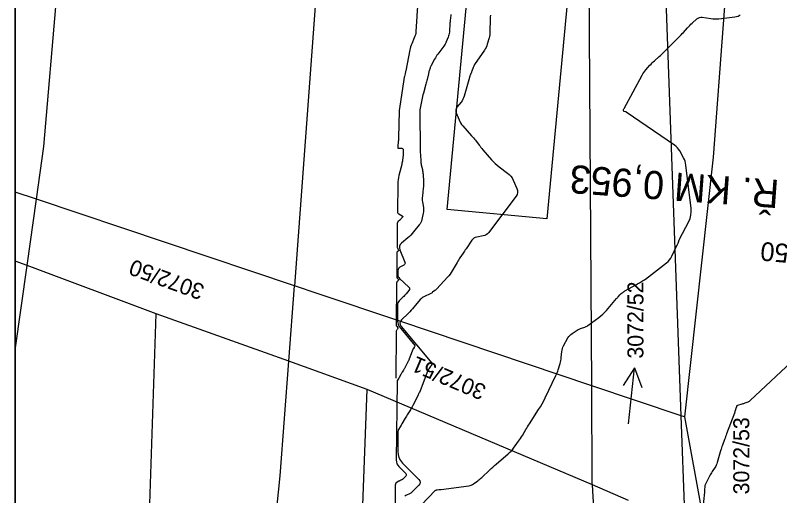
# Model space of a CAD drawing. Extents: x -534410 to -534262, y -1190162 to -1189584.
# Drawn here: x -534410.13 to -534369.46, y -1189643.39 to -1189617.8 of the extents above; entities that cross this region are included whole.
import ezdxf

# ---------------------------------------------------------------- set-up
doc = ezdxf.new("R2010")
doc.units = 0
for name, color, linetype in [('30', 7, 'Continuous'), ('31', 7, 'Continuous'), ('_N_text', 7, 'Continuous'), ('_přístup', 7, 'Continuous'), ('_rámeček', 7, 'Continuous'), ('_rámeček_mřížka', 7, 'Continuous'), ('Hranice parcel', 7, 'Continuous'), ('Parcelní čísla', 7, 'Continuous'), ('Pop  PČ popisy', 7, 'Continuous')]:
    doc.layers.add(name, color=color, linetype=linetype)

msp = doc.modelspace()

# ---------------------------------------------------------------- linework, layer by layer
at = {"layer": '30'}
for points in [[(-534386.954, -1189617.758), (-534386.98, -1189617.983), (-534386.986, -1189618.039), (-534386.992, -1189618.095), (-534386.997, -1189618.151), (-534387.001, -1189618.207), (-534387.035, -1189618.711), (-534387.043, -1189618.777), (-534387.055, -1189618.842), (-534387.072, -1189618.906), (-534387.095, -1189618.968), (-534387.197, -1189619.216), (-534387.224, -1189619.277), (-534387.255, -1189619.336), (-534387.289, -1189619.393), (-534387.328, -1189619.447), (-534387.649, -1189619.875), (-534387.695, -1189619.938), (-534387.738, -1189620.002), (-534387.779, -1189620.068), (-534387.818, -1189620.136), (-534388.005, -1189620.477), (-534388.022, -1189620.512), (-534388.038, -1189620.547), (-534388.052, -1189620.583), (-534388.063, -1189620.62), (-534388.106, -1189620.77), (-534388.117, -1189620.807), (-534388.127, -1189620.845), (-534388.136, -1189620.882), (-534388.145, -1189620.92), (-534388.214, -1189621.22), (-534388.229, -1189621.282), (-534388.245, -1189621.344), (-534388.261, -1189621.406), (-534388.278, -1189621.468), (-534388.414, -1189621.947), (-534388.438, -1189622.036), (-534388.46, -1189622.125), (-534388.481, -1189622.214), (-534388.5, -1189622.304), (-534388.573, -1189622.664), (-534388.589, -1189622.755), (-534388.6, -1189622.845), (-534388.607, -1189622.937), (-534388.609, -1189623.028), (-534388.606, -1189623.635), (-534388.605, -1189623.671), (-534388.605, -1189623.706), (-534388.604, -1189623.742), (-534388.602, -1189623.778), (-534388.597, -1189623.922), (-534388.595, -1189623.958), (-534388.595, -1189623.994), (-534388.594, -1189624.03), (-534388.594, -1189624.066), (-534388.59, -1189624.641), (-534388.589, -1189624.743), (-534388.588, -1189624.844), (-534388.585, -1189624.946), (-534388.581, -1189625.047), (-534388.56, -1189625.531), (-534388.556, -1189625.594), (-534388.549, -1189625.656), (-534388.539, -1189625.717), (-534388.527, -1189625.778), (-534388.471, -1189626.023), (-534388.458, -1189626.084), (-534388.448, -1189626.146), (-534388.44, -1189626.208), (-534388.435, -1189626.27), (-534388.411, -1189626.67), (-534388.407, -1189626.757), (-534388.408, -1189626.844), (-534388.412, -1189626.931), (-534388.42, -1189627.019), (-534388.469, -1189627.435), (-534388.475, -1189627.511), (-534388.476, -1189627.588), (-534388.472, -1189627.664), (-534388.462, -1189627.74), (-534388.415, -1189628.045), (-534388.406, -1189628.121), (-534388.405, -1189628.196), (-534388.411, -1189628.272), (-534388.424, -1189628.347), (-534388.498, -1189628.683), (-534388.52, -1189628.762), (-534388.551, -1189628.836), (-534388.59, -1189628.907), (-534388.638, -1189628.974), (-534388.938, -1189629.347), (-534389.007, -1189629.429), (-534389.08, -1189629.508), (-534389.156, -1189629.583), (-534389.236, -1189629.654), (-534389.576, -1189629.944), (-534389.644, -1189630.02), (-534389.681, -1189630.103), (-534389.687, -1189630.194), (-534389.663, -1189630.293), (-534389.404, -1189630.951), (-534389.392, -1189631.002), (-534389.398, -1189631.046), (-534389.421, -1189631.084), (-534389.463, -1189631.115), (-534389.668, -1189631.226), (-534389.712, -1189631.258), (-534389.744, -1189631.296), (-534389.763, -1189631.343), (-534389.77, -1189631.397), (-534389.772, -1189631.627), (-534389.768, -1189631.682), (-534389.752, -1189631.733), (-534389.726, -1189631.779), (-534389.689, -1189631.821), (-534389.193, -1189632.285), (-534389.159, -1189632.327), (-534389.146, -1189632.37), (-534389.154, -1189632.415), (-534389.183, -1189632.46), (-534389.34, -1189632.646), (-534389.38, -1189632.692), (-534389.421, -1189632.737), (-534389.463, -1189632.781), (-534389.506, -1189632.824), (-534389.697, -1189633.012), (-534389.738, -1189633.06), (-534389.767, -1189633.113), (-534389.785, -1189633.17), (-534389.791, -1189633.233), (-534389.798, -1189633.974), (-534389.788, -1189634.115), (-534389.754, -1189634.248), (-534389.697, -1189634.373), (-534389.616, -1189634.489), (-534388.866, -1189635.394), (-534388.861, -1189635.402), (-534388.859, -1189635.41), (-534388.86, -1189635.417), (-534388.865, -1189635.425), (-534388.888, -1189635.458), (-534388.899, -1189635.474), (-534388.91, -1189635.49), (-534388.948, -1189635.546), (-534388.955, -1189635.558), (-534388.962, -1189635.571), (-534388.968, -1189635.584), (-534388.974, -1189635.597), (-534389.136, -1189636.02), (-534389.145, -1189636.044), (-534389.155, -1189636.068), (-534389.165, -1189636.092), (-534389.175, -1189636.116), (-534389.215, -1189636.211), (-534389.226, -1189636.235), (-534389.236, -1189636.259), (-534389.248, -1189636.282), (-534389.259, -1189636.305), (-534389.401, -1189636.58), (-534389.416, -1189636.61), (-534389.433, -1189636.64), (-534389.45, -1189636.669), (-534389.468, -1189636.698), (-534389.54, -1189636.814), (-534389.558, -1189636.843), (-534389.575, -1189636.871), (-534389.593, -1189636.901), (-534389.61, -1189636.93), (-534389.708, -1189637.094), (-534389.726, -1189637.124), (-534389.762, -1189637.185), (-534389.798, -1189637.247), (-534389.805, -1189637.261), (-534389.81, -1189637.274), (-534389.813, -1189637.289), (-534389.814, -1189637.303), (-534389.856, -1189641.498), (-534389.848, -1189641.596), (-534389.822, -1189641.686), (-534389.778, -1189641.769), (-534389.716, -1189641.845), (-534389.355, -1189642.215), (-534389.331, -1189642.247), (-534389.323, -1189642.279), (-534389.331, -1189642.312), (-534389.355, -1189642.344), (-534389.516, -1189642.508), (-534389.531, -1189642.522), (-534389.546, -1189642.534), (-534389.562, -1189642.545), (-534389.579, -1189642.554), (-534389.651, -1189642.589), (-534389.668, -1189642.597), (-534389.686, -1189642.607), (-534389.703, -1189642.616), (-534389.72, -1189642.626), (-534389.857, -1189642.708), (-534389.863, -1189642.712), (-534389.868, -1189642.716), (-534389.872, -1189642.721), (-534389.875, -1189642.727), (-534389.894, -1189642.764), (-534389.903, -1189642.783), (-534389.906, -1189642.789), (-534389.908, -1189642.796), (-534389.916, -1189642.826), (-534389.917, -1189642.833), (-534389.918, -1189642.839), (-534389.919, -1189642.845), (-534389.919, -1189642.852), (-534389.936, -1189645.024)], [(-534388.521, -1189643.873), (-534387.781, -1189643.119), (-534387.761, -1189643.102), (-534387.739, -1189643.089), (-534387.715, -1189643.08), (-534387.689, -1189643.076), (-534387.579, -1189643.067), (-534387.552, -1189643.065), (-534387.525, -1189643.062), (-534387.498, -1189643.059), (-534387.471, -1189643.056), (-534385.999, -1189642.863), (-534385.931, -1189642.85), (-534385.867, -1189642.828), (-534385.805, -1189642.799), (-534385.748, -1189642.761), (-534385.522, -1189642.595), (-534385.467, -1189642.552), (-534385.413, -1189642.508), (-534385.36, -1189642.462), (-534385.308, -1189642.415), (-534384.897, -1189642.024), (-534384.81, -1189641.944), (-534384.723, -1189641.865), (-534384.635, -1189641.787), (-534384.546, -1189641.71), (-534383.905, -1189641.167), (-534383.826, -1189641.096), (-534383.752, -1189641.021), (-534383.683, -1189640.941), (-534383.618, -1189640.858), (-534383.349, -1189640.49), (-534383.297, -1189640.416), (-534383.246, -1189640.341), (-534383.197, -1189640.264), (-534383.149, -1189640.186), (-534382.964, -1189639.873), (-534382.918, -1189639.794), (-534382.87, -1189639.717), (-534382.822, -1189639.639), (-534382.773, -1189639.563), (-534382.283, -1189638.805), (-534382.187, -1189638.651), (-534382.097, -1189638.495), (-534382.011, -1189638.337), (-534381.93, -1189638.175), (-534381.361, -1189636.997), (-534381.326, -1189636.92), (-534381.294, -1189636.842), (-534381.265, -1189636.763), (-534381.239, -1189636.682), (-534381.14, -1189636.351), (-534381.119, -1189636.273), (-534381.102, -1189636.194), (-534381.089, -1189636.114), (-534381.08, -1189636.034), (-534381.052, -1189635.711), (-534381.041, -1189635.632), (-534381.022, -1189635.555), (-534380.994, -1189635.48), (-534380.959, -1189635.408), (-534380.725, -1189634.987), (-534380.682, -1189634.919), (-534380.631, -1189634.858), (-534380.574, -1189634.803), (-534380.509, -1189634.756), (-534380.176, -1189634.54), (-534380.136, -1189634.516), (-534380.095, -1189634.496), (-534380.053, -1189634.479), (-534380.009, -1189634.465), (-534379.832, -1189634.415), (-534379.788, -1189634.401), (-534379.747, -1189634.383), (-534379.707, -1189634.361), (-534379.669, -1189634.335), (-534379.079, -1189633.895), (-534378.971, -1189633.81), (-534378.867, -1189633.719), (-534378.77, -1189633.623), (-534378.677, -1189633.521), (-534378.134, -1189632.892), (-534378.114, -1189632.868), (-534378.094, -1189632.844), (-534378.074, -1189632.82), (-534378.054, -1189632.797), (-534377.973, -1189632.698), (-534377.953, -1189632.676), (-534377.932, -1189632.656), (-534377.91, -1189632.636), (-534377.887, -1189632.618), (-534377.791, -1189632.549), (-534377.767, -1189632.532), (-534377.742, -1189632.515), (-534377.717, -1189632.5), (-534377.691, -1189632.485), (-534377.07, -1189632.137), (-534377.031, -1189632.115), (-534376.992, -1189632.092), (-534376.952, -1189632.07), (-534376.913, -1189632.047), (-534376.756, -1189631.955), (-534376.718, -1189631.932), (-534376.68, -1189631.907), (-534376.643, -1189631.881), (-534376.606, -1189631.854), (-534375.485, -1189630.989), (-534375.396, -1189630.913), (-534375.318, -1189630.827), (-534375.251, -1189630.733), (-534375.195, -1189630.63), (-534374.911, -1189630.039), (-534374.899, -1189630.013), (-534374.888, -1189629.988), (-534374.878, -1189629.962), (-534374.868, -1189629.936), (-534374.83, -1189629.83), (-534374.82, -1189629.804), (-534374.809, -1189629.778), (-534374.797, -1189629.752), (-534374.785, -1189629.727), (-534374.3, -1189628.787), (-534374.229, -1189628.62), (-534374.184, -1189628.448), (-534374.166, -1189628.271), (-534374.174, -1189628.089), (-534374.45, -1189625.784), (-534374.467, -1189625.682), (-534374.494, -1189625.583), (-534374.531, -1189625.486), (-534374.577, -1189625.393), (-534374.781, -1189625.027), (-534374.836, -1189624.94), (-534374.9, -1189624.861), (-534374.973, -1189624.789), (-534375.055, -1189624.726), (-534377.622, -1189622.959), (-534377.633, -1189622.953), (-534377.644, -1189622.947), (-534377.656, -1189622.944), (-534377.668, -1189622.941), (-534377.728, -1189622.933), (-534377.735, -1189622.931), (-534377.741, -1189622.928), (-534377.747, -1189622.923), (-534377.752, -1189622.918), (-534377.773, -1189622.886), (-534377.775, -1189622.882), (-534377.776, -1189622.878), (-534377.777, -1189622.874), (-534377.778, -1189622.87), (-534377.778, -1189622.851), (-534377.778, -1189622.848), (-534377.777, -1189622.845), (-534377.776, -1189622.842), (-534377.775, -1189622.838), (-534377.769, -1189622.823), (-534377.766, -1189622.817), (-534377.764, -1189622.815), (-534377.746, -1189622.785), (-534377.74, -1189622.775), (-534377.738, -1189622.77), (-534376.78, -1189620.994), (-534376.738, -1189620.92), (-534376.691, -1189620.85), (-534376.641, -1189620.783), (-534376.586, -1189620.719), (-534376.36, -1189620.467), (-534376.302, -1189620.405), (-534376.243, -1189620.344), (-534376.183, -1189620.285), (-534376.121, -1189620.228), (-534375.869, -1189620.001), (-534375.806, -1189619.944), (-534375.745, -1189619.886), (-534375.684, -1189619.828), (-534375.623, -1189619.768), (-534374.819, -1189618.964), (-534374.76, -1189618.904), (-534374.701, -1189618.843), (-534374.643, -1189618.781), (-534374.586, -1189618.719), (-534374.36, -1189618.467), (-534374.302, -1189618.405), (-534374.243, -1189618.344), (-534374.183, -1189618.285), (-534374.121, -1189618.228), (-534373.869, -1189618.001), (-534373.803, -1189617.953), (-534373.733, -1189617.922), (-534373.657, -1189617.909), (-534373.576, -1189617.913), (-534373.119, -1189617.981), (-534373.015, -1189617.993), (-534372.911, -1189617.999), (-534372.806, -1189617.997), (-534372.702, -1189617.989), (-534371.838, -1189617.895), (-534371.678, -1189617.855), (-534371.557, -1189617.776)]]:
    msp.add_lwpolyline(points, dxfattribs=at)
at = {"layer": '31'}
for points in [[(-534388.702, -1189617.09), (-534388.76, -1189617.818), (-534388.76, -1189617.827), (-534388.761, -1189617.836), (-534388.761, -1189617.858), (-534388.761, -1189617.871), (-534388.816, -1189618.671), (-534388.826, -1189618.757), (-534388.843, -1189618.841), (-534388.866, -1189618.923), (-534388.897, -1189619.004), (-534389.035, -1189619.324), (-534389.068, -1189619.404), (-534389.095, -1189619.486), (-534389.119, -1189619.569), (-534389.138, -1189619.654), (-534389.357, -1189620.769), (-534389.364, -1189620.806), (-534389.372, -1189620.844), (-534389.381, -1189620.882), (-534389.389, -1189620.92), (-534389.424, -1189621.071), (-534389.432, -1189621.108), (-534389.44, -1189621.146), (-534389.447, -1189621.184), (-534389.453, -1189621.223), (-534389.685, -1189622.774), (-534389.687, -1189622.788), (-534389.69, -1189622.803), (-534389.696, -1189622.834), (-534389.697, -1189622.839), (-534389.698, -1189622.845), (-534389.698, -1189622.85), (-534389.698, -1189622.856), (-534389.698, -1189622.884), (-534389.699, -1189622.901), (-534389.74, -1189624.338), (-534389.742, -1189624.386), (-534389.744, -1189624.434), (-534389.747, -1189624.482), (-534389.75, -1189624.53), (-534389.769, -1189624.8), (-534389.77, -1189624.808), (-534389.771, -1189624.817), (-534389.772, -1189624.826), (-534389.774, -1189624.834), (-534389.78, -1189624.868), (-534389.781, -1189624.876), (-534389.778, -1189624.881), (-534389.774, -1189624.884), (-534389.766, -1189624.885), (-534389.565, -1189624.89), (-534389.533, -1189624.895), (-534389.51, -1189624.909), (-534389.496, -1189624.932), (-534389.49, -1189624.964), (-534389.484, -1189625.109), (-534389.483, -1189625.145), (-534389.484, -1189625.181), (-534389.486, -1189625.218), (-534389.49, -1189625.254), (-534389.524, -1189625.521), (-534389.533, -1189625.577), (-534389.542, -1189625.633), (-534389.554, -1189625.689), (-534389.567, -1189625.744), (-534389.713, -1189626.33), (-534389.738, -1189626.446), (-534389.757, -1189626.564), (-534389.769, -1189626.682), (-534389.773, -1189626.801), (-534389.789, -1189628.262), (-534389.785, -1189628.302), (-534389.771, -1189628.336), (-534389.749, -1189628.364), (-534389.716, -1189628.387), (-534389.543, -1189628.483), (-534389.524, -1189628.497), (-534389.516, -1189628.513), (-534389.517, -1189628.531), (-534389.529, -1189628.551), (-534389.598, -1189628.636), (-534389.615, -1189628.657), (-534389.634, -1189628.677), (-534389.653, -1189628.696), (-534389.673, -1189628.714), (-534389.76, -1189628.788), (-534389.778, -1189628.807), (-534389.792, -1189628.829), (-534389.8, -1189628.853), (-534389.803, -1189628.88), (-534389.815, -1189630.09), (-534389.814, -1189630.117), (-534389.81, -1189630.145), (-534389.804, -1189630.171), (-534389.795, -1189630.197), (-534389.743, -1189630.33), (-534389.74, -1189630.341), (-534389.742, -1189630.35), (-534389.747, -1189630.358), (-534389.756, -1189630.365), (-534389.799, -1189630.388), (-534389.809, -1189630.395), (-534389.815, -1189630.403), (-534389.82, -1189630.413), (-534389.821, -1189630.425), (-534389.834, -1189631.744), (-534389.832, -1189631.763), (-534389.827, -1189631.78), (-534389.818, -1189631.796), (-534389.805, -1189631.81), (-534389.734, -1189631.876), (-534389.728, -1189631.884), (-534389.726, -1189631.891), (-534389.728, -1189631.899), (-534389.733, -1189631.907), (-534389.76, -1189631.939), (-534389.766, -1189631.946), (-534389.773, -1189631.954), (-534389.781, -1189631.962), (-534389.788, -1189631.969), (-534389.821, -1189632.002), (-534389.828, -1189632.01), (-534389.833, -1189632.019), (-534389.836, -1189632.029), (-534389.837, -1189632.04), (-534389.859, -1189634.305), (-534389.857, -1189634.322), (-534389.853, -1189634.339), (-534389.846, -1189634.354), (-534389.836, -1189634.369), (-534389.768, -1189634.451), (-534389.767, -1189634.453), (-534389.776, -1189634.467), (-534389.778, -1189634.471), (-534389.795, -1189634.515), (-534389.803, -1189634.533), (-534389.806, -1189634.54), (-534389.82, -1189634.567), (-534389.825, -1189634.576), (-534389.839, -1189634.598), (-534389.855, -1189634.626), (-534389.859, -1189634.633), (-534389.86, -1189634.638), (-534389.885, -1189637.129)], [(-534384.853, -1189617.792), (-534384.858, -1189617.905), (-534384.858, -1189617.933), (-534384.859, -1189617.961), (-534384.86, -1189617.989), (-534384.861, -1189618.017), (-534384.873, -1189618.669), (-534384.877, -1189618.756), (-534384.887, -1189618.843), (-534384.903, -1189618.929), (-534384.924, -1189619.013), (-534385.019, -1189619.351), (-534385.047, -1189619.434), (-534385.08, -1189619.514), (-534385.12, -1189619.591), (-534385.167, -1189619.665), (-534385.692, -1189620.431), (-534385.716, -1189620.469), (-534385.738, -1189620.508), (-534385.757, -1189620.548), (-534385.773, -1189620.59), (-534385.843, -1189620.79), (-534385.853, -1189620.817), (-534385.863, -1189620.844), (-534385.874, -1189620.871), (-534385.885, -1189620.898), (-534385.932, -1189621.004), (-534385.943, -1189621.03), (-534385.953, -1189621.057), (-534385.962, -1189621.085), (-534385.971, -1189621.112), (-534386.252, -1189622.116), (-534386.28, -1189622.2), (-534386.316, -1189622.28), (-534386.359, -1189622.355), (-534386.41, -1189622.427), (-534386.631, -1189622.705), (-534386.675, -1189622.776), (-534386.696, -1189622.851), (-534386.696, -1189622.928), (-534386.672, -1189623.008), (-534386.52, -1189623.372), (-534386.48, -1189623.458), (-534386.433, -1189623.539), (-534386.38, -1189623.617), (-534386.32, -1189623.69), (-534385.849, -1189624.219), (-534385.797, -1189624.279), (-534385.745, -1189624.34), (-534385.695, -1189624.402), (-534385.646, -1189624.465), (-534385.451, -1189624.718), (-534385.402, -1189624.781), (-534385.352, -1189624.843), (-534385.301, -1189624.905), (-534385.25, -1189624.966), (-534384.785, -1189625.506), (-534384.694, -1189625.605), (-534384.599, -1189625.699), (-534384.498, -1189625.788), (-534384.392, -1189625.871), (-534383.939, -1189626.208), (-534383.847, -1189626.286), (-534383.767, -1189626.374), (-534383.699, -1189626.471), (-534383.642, -1189626.578), (-534383.441, -1189627.024), (-534383.406, -1189627.134), (-534383.403, -1189627.24), (-534383.43, -1189627.343), (-534383.488, -1189627.443), (-534384.956, -1189629.389), (-534385.012, -1189629.451), (-534385.077, -1189629.5), (-534385.15, -1189629.535), (-534385.231, -1189629.556), (-534385.572, -1189629.614), (-534385.653, -1189629.636), (-534385.725, -1189629.672), (-534385.787, -1189629.722), (-534385.84, -1189629.787), (-534386.145, -1189630.241), (-534386.185, -1189630.301), (-534386.226, -1189630.362), (-534386.267, -1189630.422), (-534386.307, -1189630.482), (-534386.47, -1189630.724), (-534386.511, -1189630.785), (-534386.55, -1189630.846), (-534386.588, -1189630.908), (-534386.625, -1189630.971), (-534386.879, -1189631.411), (-534386.935, -1189631.504), (-534386.997, -1189631.593), (-534387.064, -1189631.679), (-534387.135, -1189631.761), (-534387.693, -1189632.37), (-534387.718, -1189632.397), (-534387.745, -1189632.422), (-534387.774, -1189632.447), (-534387.803, -1189632.47), (-534387.923, -1189632.56), (-534387.953, -1189632.581), (-534387.985, -1189632.601), (-534388.017, -1189632.62), (-534388.051, -1189632.637), (-534388.363, -1189632.785), (-534388.424, -1189632.817), (-534388.481, -1189632.856), (-534388.533, -1189632.901), (-534388.58, -1189632.951), (-534388.921, -1189633.353), (-534388.994, -1189633.437), (-534389.069, -1189633.519), (-534389.145, -1189633.6), (-534389.223, -1189633.679), (-534389.574, -1189634.022), (-534389.638, -1189634.107), (-534389.663, -1189634.193), (-534389.647, -1189634.281), (-534389.592, -1189634.372), (-534387.964, -1189636.337), (-534387.955, -1189636.352), (-534387.951, -1189636.367), (-534387.954, -1189636.382), (-534387.962, -1189636.397), (-534388.006, -1189636.458), (-534388.017, -1189636.473), (-534388.027, -1189636.489), (-534388.038, -1189636.504), (-534388.049, -1189636.52), (-534388.119, -1189636.626), (-534388.134, -1189636.649), (-534388.147, -1189636.673), (-534388.159, -1189636.698), (-534388.17, -1189636.723), (-534388.478, -1189637.527), (-534388.496, -1189637.573), (-534388.514, -1189637.619), (-534388.533, -1189637.665), (-534388.552, -1189637.71), (-534388.629, -1189637.892), (-534388.649, -1189637.937), (-534388.669, -1189637.982), (-534388.69, -1189638.026), (-534388.712, -1189638.071), (-534388.981, -1189638.594), (-534389.011, -1189638.651), (-534389.043, -1189638.707), (-534389.075, -1189638.763), (-534389.109, -1189638.818), (-534389.246, -1189639.038), (-534389.28, -1189639.092), (-534389.314, -1189639.148), (-534389.347, -1189639.203), (-534389.38, -1189639.258), (-534389.566, -1189639.571), (-534389.583, -1189639.599), (-534389.6, -1189639.628), (-534389.659, -1189639.729), (-534389.738, -1189639.863), (-534389.75, -1189639.888), (-534389.759, -1189639.914), (-534389.765, -1189639.941), (-534389.767, -1189639.969), (-534389.778, -1189641.019), (-534389.763, -1189641.197), (-534389.716, -1189641.362), (-534389.636, -1189641.513), (-534389.523, -1189641.652), (-534388.658, -1189642.536), (-534388.605, -1189642.608), (-534388.588, -1189642.68), (-534388.605, -1189642.752), (-534388.658, -1189642.823), (-534389.019, -1189643.191), (-534389.051, -1189643.221), (-534389.085, -1189643.248), (-534389.121, -1189643.271), (-534389.16, -1189643.292), (-534389.318, -1189643.37), (-534389.358, -1189643.389), (-534389.397, -1189643.41)], [(-534368.571, -1189636.011), (-534371.025, -1189638.319), (-534371.056, -1189638.345), (-534371.089, -1189638.368), (-534371.124, -1189638.388), (-534371.161, -1189638.404), (-534371.314, -1189638.462), (-534371.352, -1189638.477), (-534371.391, -1189638.491), (-534371.429, -1189638.504), (-534371.468, -1189638.517), (-534371.699, -1189638.591), (-534371.719, -1189638.601), (-534371.736, -1189638.613), (-534371.749, -1189638.63), (-534371.758, -1189638.65), (-534371.79, -1189638.741), (-534371.797, -1189638.762), (-534371.804, -1189638.783), (-534371.81, -1189638.804), (-534371.816, -1189638.825), (-534371.84, -1189638.911), (-534371.846, -1189638.932), (-534371.853, -1189638.953), (-534371.86, -1189638.974), (-534371.867, -1189638.995), (-534372.284, -1189640.098), (-534372.312, -1189640.173), (-534372.34, -1189640.247), (-534372.368, -1189640.322), (-534372.395, -1189640.397), (-534372.506, -1189640.695), (-534372.533, -1189640.77), (-534372.558, -1189640.845), (-534372.582, -1189640.921), (-534372.604, -1189640.998), (-534372.786, -1189641.632), (-534372.807, -1189641.697), (-534372.833, -1189641.76), (-534372.863, -1189641.821), (-534372.898, -1189641.879), (-534373.048, -1189642.109), (-534373.085, -1189642.167), (-534373.12, -1189642.226), (-534373.154, -1189642.286), (-534373.186, -1189642.347), (-534373.408, -1189642.78), (-534373.423, -1189642.813), (-534373.434, -1189642.846), (-534373.441, -1189642.881), (-534373.445, -1189642.916), (-534373.452, -1189643.06), (-534373.454, -1189643.096), (-534373.457, -1189643.132), (-534373.46, -1189643.168), (-534373.463, -1189643.204), (-534373.625, -1189644.701)]]:
    msp.add_lwpolyline(points, dxfattribs=at)
at = {"layer": '_přístup'}
msp.add_lwpolyline([(-534387.143, -1189628.143), (-534385.688, -1189612.702), (-534380.389, -1189613.202), (-534381.845, -1189628.642)], close=True, dxfattribs=at)
at = {"layer": '_rámeček'}
msp.add_line((-534410.126, -1189584.47), (-534410.126, -1190161.97), dxfattribs=at)
msp.add_lwpolyline([(-534410.126, -1189584.47), (-534261.626, -1189584.47), (-534261.626, -1189689.47), (-534410.126, -1189689.47)], close=True, dxfattribs=at)
at = {"layer": '_rámeček_mřížka'}
msp.add_line((-534410.126, -1189584.47), (-534410.126, -1190161.97), dxfattribs=at)
at = {"layer": 'Hranice parcel'}
for p, q in [((-534408.99, -1189627.6), (-534410.126, -1189627.218)), ((-534409.49, -1189631.14), (-534408.99, -1189627.6)), ((-534395.28, -1189632.21), (-534408.99, -1189627.6)), ((-534409.49, -1189631.14), (-534410.126, -1189630.901)), ((-534410.126, -1189635.647), (-534409.49, -1189631.14)), ((-534402.64, -1189633.7), (-534409.49, -1189631.14)), ((-534395.58, -1189636.23), (-534395.28, -1189632.21)), ((-534394.01, -1189632.64), (-534395.28, -1189632.21)), ((-534389.73, -1189634.08), (-534394.01, -1189632.64)), ((-534404.82, -1189701), (-534402.64, -1189633.7)), ((-534395.58, -1189636.23), (-534402.64, -1189633.7)), ((-534379.46, -1189637.54), (-534389.73, -1189634.08)), ((-534391.41, -1189637.73), (-534395.58, -1189636.23)), ((-534394.19, -1189710.57), (-534391.41, -1189637.73)), ((-534379.42, -1189642.82), (-534391.41, -1189637.73)), ((-534374.7, -1189639.14), (-534379.46, -1189637.54)), ((-534374.42, -1189646.7), (-534374.7, -1189639.14)), ((-534374.52, -1189639.2), (-534374.7, -1189639.14)), ((-534374.52, -1189639.2), (-534371.04, -1189658.4)), ((-534377.8, -1189671.05), (-534379.42, -1189642.82)), ((-534377.5, -1189643.64), (-534379.42, -1189642.82))]:
    msp.add_line(p, q, dxfattribs=at)
for points in [[(-534408.99, -1189627.6), (-534408.6, -1189624.8), (-534405.151, -1189584.47)], [(-534391.623, -1189584.47), (-534392.21, -1189590.63), (-534395.28, -1189632.21)], [(-534379.46, -1189637.54), (-534379.76, -1189591.95), (-534379.572, -1189584.47)], [(-534374.7, -1189639.14), (-534376.664, -1189584.47)], [(-534369.94, -1189584.47), (-534373, -1189625.37), (-534374.52, -1189639.2)], [(-534402.1, -1189701.89), (-534396.03, -1189642.33), (-534395.58, -1189636.23)], [(-534379.42, -1189642.82), (-534379.43, -1189642.72), (-534379.46, -1189637.54)]]:
    msp.add_lwpolyline(points, dxfattribs=at)
at = {"layer": 'Pop  PČ popisy'}
for p, q in [((-534377.185, -1189636.573), (-534377.788, -1189637.517)), ((-534377.499, -1189639.558), (-534377.185, -1189636.573)), ((-534377.185, -1189636.573), (-534376.792, -1189637.622))]:
    msp.add_line(p, q, dxfattribs=at)

# ---------------------------------------------------------------- texts
at = {"layer": '_N_text'}
for s, height, rotation, p in [('Ř. KM 0,953', 1.5, 175.8075, (-534369.444, -1189626.585)), ('950', 1, 175.0404, (-534368.21, -1189630.061))]:
    msp.add_text(s, height=height, rotation=rotation, dxfattribs=at).set_placement(p)
at = {"layer": 'Parcelní čísla'}
for s, rotation, p in [('3072/50', 160, (-534400, -1189632.187)), ('3072/52', 90, (-534376.71, -1189636.091)), ('3072/51', 157, (-534385.011, -1189637.545)), ('3072/53', 90, (-534371.078, -1189643.322))]:
    msp.add_text(s, height=0.85, rotation=rotation, dxfattribs=at).set_placement(p)

doc.saveas('drawing.dxf')
